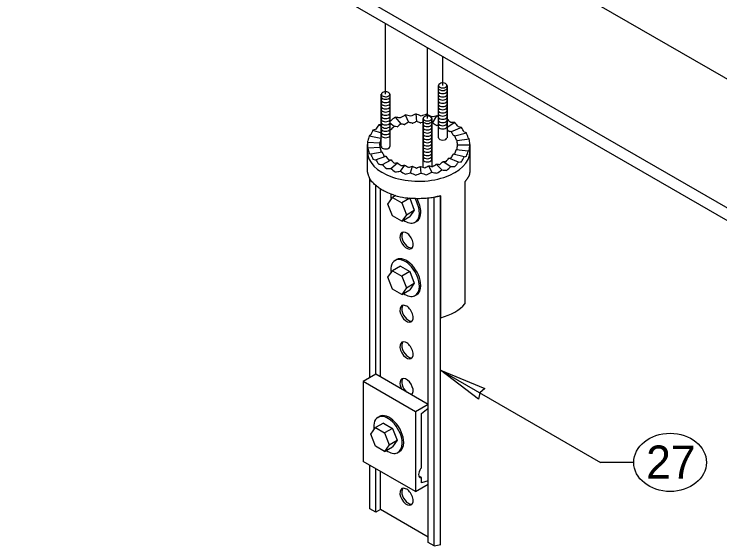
# Model space of a CAD drawing. Extents: x 99862 to 104211, y 98939 to 105076.
# Drawn here: x 101812.5 to 102152.3, y 103360.8 to 103616.7 of the extents above; entities that cross this region are included whole.
import ezdxf

# ---------------------------------------------------------------- set-up
doc = ezdxf.new("R2010")
doc.units = 0
for name, color, linetype in [('Default', 7, 'Continuous'), ('Level 1', 7, 'Continuous'), ('Level 12', 7, 'Continuous'), ('Level 13', 7, 'Continuous'), ('Level 15', 7, 'Continuous'), ('Level 20', 7, 'Continuous'), ('Level 21', 7, 'Continuous'), ('Level 7', 7, 'Continuous')]:
    doc.layers.add(name, color=color, linetype=linetype)

msp = doc.modelspace()

# ---------------------------------------------------------------- linework, layer by layer
at = {"layer": 'Default'}
for p, q in [((102016.79, 103557.27), (102016.79, 103582.44)), ((102016.79, 103557.27), (102016.79, 103582.44)), ((102020.9, 103582.44), (102020.9, 103557.27)), ((102020.9, 103582.44), (102020.9, 103557.27)), ((101989.28, 103553.02), (101989.28, 103578.18)), ((101989.28, 103553.02), (101989.28, 103578.18)), ((101993.39, 103578.18), (101993.39, 103553.02)), ((101993.39, 103578.18), (101993.39, 103553.02)), ((102009.42, 103543.02), (102009.42, 103566.56)), ((102009.42, 103543.02), (102009.42, 103566.56)), ((102013.53, 103566.56), (102013.53, 103543.46)), ((102013.53, 103566.56), (102013.53, 103543.46)), ((101982.56, 103542.17), (101982.56, 103550.56)), ((102031.88, 103550.56), (102031.88, 103542.17)), ((101983.73, 103441.71), (101983.73, 103537.83)), ((102029.47, 103536.03), (102029.47, 103477.31)), ((101986.63, 103443.39), (101986.63, 103534.34)), ((101988.81, 103442.13), (101988.81, 103532.7)), ((102017.84, 103529.32), (102017.84, 103470.6)), ((102017.84, 103361.54), (102017.84, 103529.32)), ((102011.82, 103362.5), (102011.82, 103528.19)), ((102014.72, 103528.61), (102014.72, 103528.61)), ((102014.72, 103360.83), (102014.72, 103528.61)), ((101986.63, 103443.39), (101980.56, 103439.88)), ((102011.82, 103428.84), (101986.63, 103443.39)), ((102005.75, 103425.34), (101980.56, 103439.88)), ((101980.56, 103439.88), (101980.56, 103401.51)), ((102011.82, 103428.84), (102005.75, 103425.34)), ((102008.66, 103424.48), (102011.82, 103427.16)), ((102011.82, 103427.16), (102011.82, 103428.84)), ((102005.75, 103425.34), (102005.75, 103386.96)), ((102008.66, 103398.44), (102008.66, 103424.48)), ((102005.75, 103386.96), (101980.56, 103401.51)), ((101983.73, 103378.72), (101983.73, 103399.68)), ((101986.63, 103377.05), (101986.63, 103398)), ((101988.81, 103378.31), (101988.81, 103396.74)), ((102008.66, 103393.69), (102007.33, 103394.46)), ((102008.66, 103391.18), (102008.66, 103393.69)), ((102005.75, 103386.96), (102011.82, 103390.47)), ((102011.79, 103392.13), (102008.66, 103391.18)), ((101986.63, 103377.05), (101983.73, 103378.72)), ((101988.81, 103378.31), (101986.63, 103377.05)), ((102011.82, 103365.02), (101988.81, 103378.31)), ((102014.72, 103360.83), (102011.82, 103362.5))]:
    msp.add_line(p, q, dxfattribs=at)
for centre, major_axis, start_param, end_param in [((102018.84, 103582.44), (2.05, 0), 2.356194, 3.141593), ((102018.84, 103582.44), (2.05, 0), 2.356194, 3.141593), ((102018.84, 103582.44), (2.05, 0), 0, 2.356194), ((102018.84, 103582.44), (2.05, 0), 0, 2.356194), ((102018.84, 103582.44), (2.05, 0), 3.141593, 6.283185), ((102018.84, 103582.44), (2.05, 0), 3.141593, 6.283185), ((101991.34, 103578.18), (2.05, 0), 0, 3.141593), ((101991.34, 103578.18), (2.05, 0), 0, 3.141593), ((101991.34, 103578.18), (2.05, 0), 3.141593, 4.45059), ((101991.34, 103578.18), (2.05, 0), 3.141593, 4.45059), ((101991.34, 103578.18), (2.05, 0), 4.45059, 6.283185), ((101991.34, 103578.18), (2.05, 0), 4.45059, 6.283185), ((102011.47, 103566.56), (2.05, 0), 0.261799, 3.141593), ((102011.47, 103566.56), (2.05, 0), 0.261799, 3.141593), ((102011.47, 103566.56), (2.05, 0), 3.141593, 6.283185), ((102011.47, 103566.56), (2.05, 0), 3.141593, 6.283185), ((102011.47, 103566.56), (2.05, 0), 0, 0.261799), ((102011.47, 103566.56), (2.05, 0), 0, 0.261799), ((102018.84, 103557.27), (2.05, 0), 3.141593, 6.283185), ((102018.84, 103557.27), (2.05, 0), 3.141593, 6.283185), ((101991.34, 103553.02), (2.05, 0), 3.141593, 4.45059), ((101991.34, 103553.02), (2.05, 0), 3.141593, 4.45059), ((101991.34, 103553.02), (2.05, 0), 4.45059, 6.283185), ((101991.34, 103553.02), (2.05, 0), 4.45059, 6.283185), ((102007.22, 103542.17), (24.66, 0), 5.021668, 5.15795), ((102001.41, 103507.78), (2.25, -3.89), 0, 3.739442), ((102002.31, 103508.3), (-2.25, 3.89), 0.203431, 2.356194), ((102001.41, 103507.78), (2.25, -3.89), 3.739442, 6.283185), ((102002.31, 103508.3), (-2.25, 3.89), 2.356194, 2.938162), ((102001.41, 103472.54), (2.25, -3.89), 3.739442, 6.283185), ((102001.41, 103472.54), (2.25, -3.89), 0, 3.739442), ((102002.31, 103473.07), (-2.25, 3.89), 0.203431, 2.356194), ((102007.22, 103483.45), (24.66, 0), 5.15795, 5.837624), ((102002.31, 103473.07), (-2.25, 3.89), 2.356194, 2.938162), ((102001.41, 103454.92), (2.25, -3.89), 3.739442, 6.283185), ((102001.41, 103454.92), (2.25, -3.89), 0, 3.739442), ((102002.31, 103455.45), (-2.25, 3.89), 0.203431, 2.356194), ((102002.31, 103455.45), (-2.25, 3.89), 2.356194, 2.938162), ((102001.41, 103437.31), (2.25, -3.89), 0.053055, 3.739442), ((102002.31, 103437.83), (-2.25, 3.89), 0.203431, 2.052802), ((102001.41, 103437.31), (2.25, -3.89), 3.739442, 4.659334), ((102002.31, 103437.83), (-2.25, 3.89), 2.659587, 2.938162), ((102009.39, 103396.48), (-1.54, -2.67), 4.266828, 6.283185), ((102009.39, 103396.48), (-1.54, -2.67), 6.283185, 6.728747), ((102001.41, 103384.46), (2.25, -3.89), 3.739442, 6.283185), ((102001.41, 103384.46), (2.25, -3.89), 0, 3.739442), ((102002.31, 103384.98), (-2.25, 3.89), 0.203431, 2.356194), ((102002.31, 103384.98), (-2.25, 3.89), 2.356194, 2.938162), ((102007.22, 103374.39), (24.66, 0), 5.021668, 5.15795)]:
    msp.add_ellipse(centre, major_axis=major_axis, ratio=0.57735, start_param=start_param, end_param=end_param, dxfattribs=at)
for points, degree in [([(102017.84, 103529.32), (102017.2, 103529.14), (102016.55, 103528.99), (102015.89, 103528.84), (102013.08, 103528.24), (102010.07, 103527.92), (102007.07, 103527.93), (102002.01, 103527.95), (101996.98, 103528.89), (101992.86, 103530.59), (101990.61, 103531.52), (101988.64, 103532.67), (101987.05, 103533.98), (101985.08, 103535.6), (101983.7, 103537.44), (101983.04, 103539.38), (101982.99, 103539.51), (101982.95, 103539.64), (101982.91, 103539.76), (101982.88, 103539.9), (101982.84, 103540.03), (101982.8, 103540.17), (101982.77, 103540.3), (101982.74, 103540.44), (101982.71, 103540.57), (101982.69, 103540.71), (101982.66, 103540.84), (101982.65, 103540.98), (101982.63, 103541.12), (101982.61, 103541.25), (101982.6, 103541.39), (101982.58, 103541.52), (101982.57, 103541.66), (101982.57, 103541.8), (101982.56, 103541.92), (101982.56, 103542.05), (101982.56, 103542.17)], 3), ([(102031.88, 103542.17), (102031.88, 103540.06), (102031.05, 103537.94), (102029.47, 103536.03)], 2)]:
    msp.add_open_spline(points, degree=degree, dxfattribs=at)
at = {"layer": 'Level 1'}
for centre in [(102018.84, 103581.24), (102018.84, 103579.7), (101991.34, 103576.98), (102018.84, 103578.15), (102018.84, 103576.61), (101991.34, 103575.44), (101991.34, 103573.9), (102018.84, 103575.07), (102018.84, 103573.53), (101991.34, 103572.36), (101991.34, 103570.82), (101991.34, 103569.28), (102018.84, 103571.99), (102018.84, 103570.45), (101991.34, 103567.74), (101991.34, 103566.2), (102018.84, 103568.91), (102018.84, 103567.37), (102018.84, 103565.83), (101991.34, 103564.66), (101991.34, 103563.11), (102011.47, 103565.36), (102011.47, 103563.82), (102018.84, 103564.29), (102018.84, 103562.75), (101991.34, 103561.57), (101991.34, 103560.03), (102011.47, 103562.28), (102011.47, 103560.74), (102011.47, 103559.19), (101991.34, 103558.49), (102011.47, 103557.65), (102011.47, 103556.11), (102011.47, 103554.57), (102011.47, 103553.03), (102011.47, 103551.49), (102011.47, 103549.95), (102011.47, 103548.41), (102011.47, 103546.87)]:
    msp.add_ellipse(centre, major_axis=(-2.13, 0), ratio=0.57735, start_param=6.018236, end_param=9.687845, dxfattribs=at)
at = {"layer": 'Level 12'}
msp.add_line((102255.59, 103465.87), (101758.84, 103752.66), dxfattribs=at)
at = {"layer": 'Level 13'}
for p, q in [((101996.02, 103567.15), (101998.71, 103563.87)), ((102000.83, 103568.21), (102002.36, 103564.68)), ((102005.93, 103568.68), (102006.24, 103565.03)), ((102011.08, 103568.52), (102010.86, 103567.69)), ((102013.93, 103564.33), (102016.06, 103567.75)), ((101988.04, 103563.41), (101989.28, 103562.77)), ((101995.42, 103562.64), (101993.39, 103564.21)), ((101996.86, 103562.58), (101997.15, 103562.69)), ((102000.34, 103563.62), (102000.66, 103563.69)), ((102004.11, 103564.23), (102004.45, 103564.26)), ((102008.03, 103564.37), (102008.37, 103564.36)), ((102015.57, 103563.24), (102015.88, 103563.15)), ((102024.66, 103564.53), (102020.9, 103562.15)), ((101985.24, 103560.92), (101989.28, 103559.55)), ((101993.84, 103561.14), (101994.08, 103561.28)), ((102021.68, 103560.44), (102021.89, 103560.29)), ((102027.91, 103562.21), (102022.94, 103560.12)), ((102024.72, 103558.1), (102030.25, 103559.56)), ((101983.39, 103558.14), (101989.11, 103557.03)), ((102023.84, 103558.56), (102024, 103558.38)), ((102025.28, 103556.45), (102025.37, 103556.26)), ((102025.73, 103555.92), (102031.58, 103556.68)), ((101982.56, 103550.77), (101982.55, 103553.97)), ((101982.58, 103555.2), (101988.5, 103554.79)), ((101988.7, 103552.53), (101982.85, 103552.23)), ((102031.85, 103553.71), (102025.94, 103553.66)), ((102031.89, 103553.97), (102031.88, 103550.56)), ((101989.72, 103550.35), (101984.18, 103549.35)), ((102029.2, 103547.99), (102023.92, 103549.31)), ((102031.05, 103550.77), (102025.32, 103551.42)), ((101986.53, 103546.7), (101991.49, 103548.33)), ((101989.77, 103544.39), (101993.96, 103546.57)), ((102019.01, 103545.81), (102022.73, 103543.38)), ((102026.39, 103545.49), (102021.79, 103547.41)), ((101993.78, 103542.51), (101997.01, 103545.15)), ((102000.5, 103544.12), (101998.38, 103541.16)), ((102003.36, 103540.39), (102004.28, 103543.53)), ((102008.51, 103540.23), (102008.2, 103543.42)), ((102013.6, 103540.7), (102012.07, 103543.77)), ((102018.42, 103541.77), (102015.73, 103544.58))]:
    msp.add_line(p, q, dxfattribs=at)
for centre, major_axis, ratio, start_param, end_param in [((102007.22, 103553.49), (22.78, 14.55), 0.650745, 1.648089, 1.752809), ((102007.22, 103553.49), (-24.35, 10.27), 0.386234, 5.240379, 5.345098), ((102007.22, 103553.49), (23.26, 13.98), 0.588004, 1.492908, 1.597627), ((102007.22, 103553.49), (-24.14, 11.57), 0.440657, 5.077658, 5.182378), ((102007.22, 103553.49), (23.67, 13.17), 0.527399, 1.337713, 1.442432), ((102007.22, 103553.49), (-23.85, 12.69), 0.497899, 4.918981, 5.0237), ((102007.22, 103553.49), (24, 12.15), 0.468967, 1.180574, 1.285294), ((102007.22, 103553.49), (-23.48, 13.6), 0.557438, 4.763018, 4.867737), ((102007.22, 103553.49), (24.25, 10.94), 0.413044, 1.020027, 1.124747), ((102007.22, 103553.49), (-23.03, 14.3), 0.6191, 4.680965, 4.712837), ((102007.22, 103553.49), (-22.52, 14.74), 0.682966, 4.451913, 4.544797), ((102007.22, 103553.49), (21.8, 14.74), 0.783391, 1.97431, 2.078685), ((102007.22, 103553.49), (-24.58, 7.12), 0.292084, 5.610582, 5.687241), ((102007.22, 103553.49), (-24.49, 8.79), 0.335596, 5.40825, 5.427057), ((102007.22, 103553.49), (-17.31, -11.06), 0.650745, 4.789682, 4.885287), ((102007.22, 103553.49), (18.5, -7.8), 0.386234, 2.1079, 2.203506), ((102007.22, 103553.49), (-17.67, -10.62), 0.588004, 4.6345, 4.730106), ((102007.22, 103553.49), (18.34, -8.79), 0.440657, 1.94518, 2.040785), ((102007.22, 103553.49), (-17.99, -10.01), 0.527399, 4.479305, 4.574911), ((102007.22, 103553.49), (18.12, -9.64), 0.497899, 1.786502, 1.882108), ((102007.22, 103553.49), (-18.24, -9.24), 0.468967, 4.361567, 4.417772), ((102007.22, 103553.49), (-18.43, -8.31), 0.413044, 4.16162, 4.184791), ((102007.22, 103553.49), (17.5, -10.86), 0.6191, 1.475639, 1.571245), ((102007.22, 103553.49), (-18.56, -7.26), 0.360362, 4.036609, 4.092053), ((102007.22, 103553.49), (24.54, 7.99), 0.312139, 0.684077, 0.788796), ((102007.22, 103553.49), (-22.02, 14.85), 0.749264, 4.290148, 4.394868), ((102007.22, 103553.49), (21.64, 13.89), 0.853385, 2.16914, 2.27386), ((102007.22, 103553.49), (-24.63, 5.38), 0.252109, 5.762237, 5.866957), ((102007.22, 103553.49), (18.68, -5.41), 0.292084, 2.449758, 2.484365), ((102007.22, 103553.49), (-16.95, -11.19), 0.716006, 4.951048, 5.046939), ((102007.22, 103553.49), (18.61, -6.68), 0.335596, 2.275771, 2.371031), ((102007.22, 103553.49), (16.73, -11.28), 0.749264, 1.15767, 1.220703), ((102007.22, 103553.49), (-18.7, -4.78), 0.270119, 3.648676, 3.744282), ((102007.22, 103553.49), (16.45, -10.98), 0.818147, 0.980127, 1.075733), ((102007.22, 103553.49), (24.61, 6.29), 0.270119, 0.507084, 0.611804), ((102007.22, 103553.49), (-21.65, 14.45), 0.818147, 4.112606, 4.217325), ((102007.22, 103553.49), (24.65, 4.45), 0.236491, 0.323887, 0.428607), ((102007.22, 103553.49), (-21.89, 12.81), 0.888613, 3.882951, 3.987671), ((102007.22, 103553.49), (22.69, 10.5), 0.922162, 2.476441, 2.581161), ((102007.22, 103553.49), (-24.66, 3.49), 0.223561, 5.948263, 6.052982), ((102007.22, 103553.49), (-17.24, -7.98), 0.922162, 5.618034, 5.71364), ((102007.22, 103553.49), (18.74, -2.65), 0.223561, 2.877532, 2.91139), ((102007.22, 103553.49), (-18.73, -3.38), 0.236491, 3.46548, 3.561085), ((102007.22, 103553.49), (16.63, -9.73), 0.888613, 0.750473, 0.846078), ((102007.22, 103553.49), (-18.74, -1.9), 0.213589, 3.276978, 3.372583), ((102007.22, 103553.49), (18.42, -3.66), 0.947565, 0.23845, 0.34317), ((102007.22, 103553.49), (24.66, 2.51), 0.213589, 0.135385, 0.240105), ((102007.22, 103553.49), (-24.24, 4.82), 0.947565, 3.380043, 3.484762), ((102007.22, 103553.49), (-24.24, 4.82), 0.947565, 0.13373, 0.23845), ((102007.22, 103553.49), (-24.67, 1.51), 0.206802, 6.138761, 6.243481), ((102007.22, 103553.49), (24.67, 0.5), 0.203365, 3.189796, 3.294515), ((102007.22, 103553.49), (-18.75, -0.38), 0.203365, 6.245101, 6.436108), ((102007.22, 103553.49), (18.42, -3.66), 0.947565, 3.275323, 3.36161), ((102007.22, 103553.49), (18.74, -1.15), 0.206802, 3.006283, 3.101888), ((102007.22, 103553.55), (-18.75, 0), 0.57735, 6.116991, 6.13522), ((102007.22, 103553.49), (16.63, -9.73), 0.888613, 3.778231, 3.882951), ((102007.22, 103553.49), (-17.24, -7.98), 0.922162, 2.581161, 2.685881), ((102007.22, 103553.49), (-18.75, -0.38), 0.203365, 3.085076, 3.189796), ((102007.22, 103553.49), (22.69, 10.5), 0.922162, 5.722754, 5.827474), ((102007.22, 103553.49), (24.67, 0.5), 0.203365, 6.226668, 6.331388), ((102007.22, 103550.56), (24.66, 0), 0.57735, 3.127072, 6.283185), ((102007.22, 103553.49), (-21.89, 12.81), 0.888613, 0.636639, 0.741359), ((102007.22, 103553.49), (24.66, 2.51), 0.213589, 3.381698, 3.486418), ((102007.22, 103553.49), (-21.65, 14.45), 0.818147, 0.866293, 0.971013), ((102007.22, 103553.49), (-18.74, -1.9), 0.213589, 0.240105, 0.344825), ((102007.22, 103553.49), (16.45, -10.98), 0.818147, 4.007886, 4.112606), ((102007.22, 103553.49), (-16.57, -11.2), 0.783391, 2.078685, 2.183404), ((102007.22, 103553.49), (18.74, -2.65), 0.223561, 5.843543, 5.948263), ((102007.22, 103553.49), (-16.44, -10.55), 0.853385, 2.27386, 2.378579), ((102007.22, 103553.49), (18.74, -1.15), 0.206802, 6.034041, 6.138761), ((102007.22, 103553.49), (21.64, 13.89), 0.853385, 5.415452, 5.520172), ((102007.22, 103553.49), (-24.67, 1.51), 0.206802, 2.892449, 2.997168), ((102007.22, 103553.49), (24.65, 4.45), 0.236491, 3.570199, 3.674919), ((102007.22, 103553.49), (-22.02, 14.85), 0.749264, 1.043836, 1.148555), ((102007.22, 103553.49), (-18.73, -3.38), 0.236491, 0.428607, 0.533326), ((102007.22, 103553.49), (16.73, -11.28), 0.749264, 4.185428, 4.290148), ((102007.22, 103553.49), (-18.7, -4.78), 0.270119, 0.611804, 0.716523), ((102007.22, 103553.49), (17.12, -11.2), 0.682966, 4.347193, 4.451913), ((102007.22, 103553.49), (-17.31, -11.06), 0.650745, 1.752809, 1.857183), ((102007.22, 103553.49), (18.68, -5.41), 0.292084, 5.477111, 5.582176), ((102007.22, 103553.49), (-16.95, -11.19), 0.716006, 1.914521, 2.019586), ((102007.22, 103553.49), (18.72, -4.09), 0.252109, 5.657863, 5.762237), ((102007.22, 103553.49), (-24.63, 5.38), 0.252109, 2.51627, 2.620645), ((102007.22, 103553.49), (21.8, 14.74), 0.783391, 5.220277, 5.324997), ((102007.22, 103553.49), (-24.66, 3.49), 0.223561, 2.70195, 2.80667), ((102007.22, 103553.49), (24.61, 6.29), 0.270119, 3.753396, 3.858116), ((102007.22, 103553.49), (-22.52, 14.74), 0.682966, 1.2056, 1.31032), ((102007.22, 103553.49), (24.54, 7.99), 0.312139, 3.930389, 4.035109), ((102007.22, 103553.49), (-23.03, 14.3), 0.6191, 1.361805, 1.466525), ((102007.22, 103553.49), (-18.65, -6.07), 0.312139, 0.788796, 0.893516), ((102007.22, 103553.49), (17.5, -10.86), 0.6191, 4.503398, 4.608118), ((102007.22, 103553.49), (-18.56, -7.26), 0.360362, 0.959575, 1.064294), ((102007.22, 103553.49), (17.84, -10.34), 0.557438, 4.658298, 4.763018), ((102007.22, 103553.49), (-18.43, -8.31), 0.413044, 1.124747, 1.229466), ((102007.22, 103553.49), (18.12, -9.64), 0.497899, 4.814261, 4.918981), ((102007.22, 103553.49), (-18.24, -9.24), 0.468967, 1.285294, 1.390013), ((102007.22, 103553.49), (18.34, -8.79), 0.440657, 4.972938, 5.077658), ((102007.22, 103553.49), (-17.99, -10.01), 0.527399, 1.442432, 1.547152), ((102007.22, 103553.49), (18.5, -7.8), 0.386234, 5.135659, 5.240379), ((102007.22, 103553.49), (-17.67, -10.62), 0.588004, 1.597627, 1.702347), ((102007.22, 103553.49), (18.61, -6.68), 0.335596, 5.30353, 5.40825), ((102007.22, 103553.49), (22.78, 14.55), 0.650745, 4.894402, 4.998776), ((102007.22, 103553.49), (-24.58, 7.12), 0.292084, 2.335518, 2.440583), ((102007.22, 103553.49), (22.3, 14.73), 0.716006, 5.056114, 5.161179), ((102007.22, 103553.49), (24.43, 9.55), 0.360362, 4.101167, 4.205887), ((102007.22, 103553.49), (-23.48, 13.6), 0.557438, 1.516705, 1.621425), ((102007.22, 103553.49), (24.25, 10.94), 0.413044, 4.266339, 4.371059), ((102007.22, 103553.49), (-23.85, 12.69), 0.497899, 1.672668, 1.777388), ((102007.22, 103553.49), (24, 12.15), 0.468967, 4.426886, 4.531606), ((102007.22, 103553.49), (-24.14, 11.57), 0.440657, 1.831346, 1.936066), ((102007.22, 103553.49), (23.67, 13.17), 0.527399, 4.584025, 4.688745), ((102007.22, 103553.49), (-24.35, 10.27), 0.386234, 1.994066, 2.098786), ((102007.22, 103553.49), (23.26, 13.98), 0.588004, 4.73922, 4.84394), ((102007.22, 103553.49), (-24.49, 8.79), 0.335596, 2.161937, 2.266657)]:
    msp.add_ellipse(centre, major_axis=major_axis, ratio=ratio, start_param=start_param, end_param=end_param, dxfattribs=at)
at = {"layer": 'Level 15'}
for p, q in [((101991.34, 103578.18), (101991.34, 103612.24)), ((102011.47, 103566.56), (102011.47, 103600.61)), ((102018.84, 103582.44), (102018.84, 103596.36)), ((102017.84, 103445.43), (102094.81, 103401)), ((102110.81, 103401), (102094.81, 103401))]:
    msp.add_line(p, q, dxfattribs=at)
msp.add_lwpolyline([(102017.84, 103445.43), (102039.11, 103436.6), (102036.7, 103434.55), (102036.12, 103431.43)], close=True, dxfattribs=at)
at = {"layer": 'Level 20'}
msp.add_ellipse((102128.31, 103401), major_axis=(-17.5, 0), ratio=0.8, dxfattribs=at)
at = {"layer": 'Level 21'}
for p, q in [((102255.59, 103459.67), (101758.84, 103746.47)), ((102030.49, 103657.79), (102269.42, 103519.84))]:
    msp.add_line(p, q, dxfattribs=at)
at = {"layer": 'Level 7'}
for p, q in [((101996.26, 103529.42), (101994.67, 103528.49)), ((102002.94, 103528.15), (101999.1, 103525.93)), ((102001.32, 103520.22), (102005.15, 103522.44)), ((101999.1, 103517.07), (102002.94, 103519.29)), ((102006.27, 103516.97), (102005.59, 103516.57)), ((101995.86, 103498.19), (101996.54, 103498.58)), ((101998.51, 103495.48), (101994.67, 103493.26)), ((102002.94, 103492.92), (101999.1, 103490.7)), ((102001.32, 103484.99), (102005.15, 103487.2)), ((101999.1, 103481.84), (102002.94, 103484.05)), ((102006.27, 103481.73), (102005.59, 103481.34)), ((101987.61, 103422.66), (101988.29, 103423.05)), ((101990.26, 103419.94), (101986.42, 103417.73)), ((101994.69, 103417.38), (101990.85, 103415.17)), ((101993.07, 103409.45), (101996.91, 103411.67)), ((101990.85, 103406.3), (101994.69, 103408.52)), ((101998.02, 103406.2), (101997.34, 103405.8))]:
    msp.add_line(p, q, dxfattribs=at)
for points in [[(101994.67, 103528.49), (101999.1, 103525.93), (102001.32, 103520.22), (101999.1, 103517.07), (101994.67, 103519.63), (101992.45, 103525.34)], [(101994.67, 103493.26), (101999.1, 103490.7), (102001.32, 103484.99), (101999.1, 103481.84), (101994.67, 103484.39), (101992.45, 103490.11)], [(101986.42, 103417.73), (101990.85, 103415.17), (101993.07, 103409.45), (101990.85, 103406.3), (101986.42, 103408.86), (101984.2, 103414.57)]]:
    msp.add_lwpolyline(points, close=True, dxfattribs=at)
for points in [[(102002.94, 103528.15), (102005.15, 103522.44), (102002.94, 103519.29)], [(101998.51, 103495.48), (102002.94, 103492.92), (102005.15, 103487.2), (102002.94, 103484.05)], [(101990.26, 103419.94), (101994.69, 103417.38), (101996.91, 103411.67), (101994.69, 103408.52)]]:
    msp.add_lwpolyline(points, dxfattribs=at)
for centre, start_param, end_param in [((102000.72, 103525), 3.768217, 4.107514), ((102000.72, 103525), 0.785398, 1.589831), ((102001.41, 103525.39), 0.785398, 1.539778), ((102000.72, 103525), 5.384089, 7.068583), ((102001.41, 103525.39), 6.283176, 7.068583), ((102000.72, 103489.76), 0.785398, 4.107514), ((102001.41, 103490.16), 0.785398, 3.141597), ((102000.72, 103489.76), 5.384089, 7.068583), ((102001.41, 103490.16), 6.283176, 7.068583), ((101992.47, 103414.23), 0.785398, 4.107514), ((101993.16, 103414.62), 0.785398, 3.141597), ((101992.47, 103414.23), 5.384089, 7.068583), ((101993.16, 103414.62), 6.283176, 7.068583)]:
    msp.add_ellipse(centre, major_axis=(4.86, -8.43), ratio=0.57735, start_param=start_param, end_param=end_param, dxfattribs=at)

# ---------------------------------------------------------------- texts
at = {"layer": 'Level 20'}
msp.add_text('27', height=16, dxfattribs=at).set_placement((102116.76, 103393.13))

doc.saveas('drawing.dxf')
